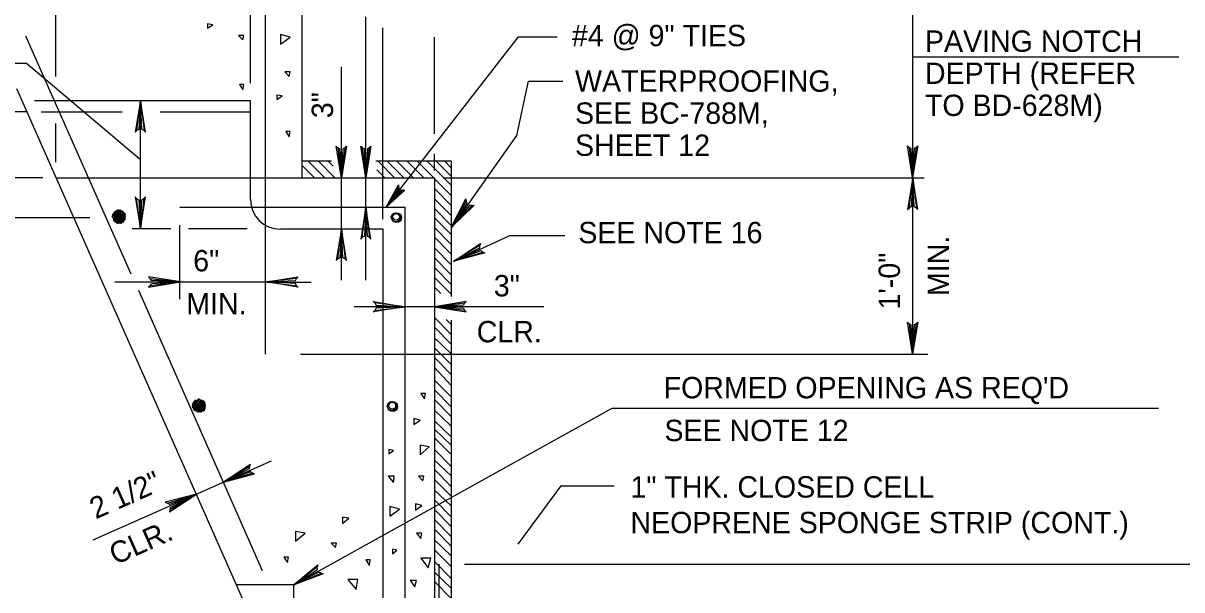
# Model space of a CAD drawing. Extents: x 640009 to 641706, y 298547 to 299735.
# Drawn here: x 640180 to 640342.7, y 299554.2 to 299633.8 of the extents above; entities that cross this region are included whole.
import ezdxf

# ---------------------------------------------------------------- set-up
doc = ezdxf.new("R2010")
doc.units = 0
doc.layers.add('1', color=7, linetype='Continuous')

msp = doc.modelspace()

# ---------------------------------------------------------------- linework, layer by layer
at = {"layer": '1'}
for p, q in [((640184.52, 299677.64), (640184.52, 299626.29)), ((640211.84, 299656.21), (640211.84, 299625.33)), ((640219.09, 299645.05), (640219.09, 299612.05)), ((640304.9, 299612.05), (640304.9, 299645.05)), ((640213.97, 299639.8), (640213.97, 299621.92)), ((640228.09, 299597.69), (640228.09, 299634.64)), ((640195.13, 299598.55), (640180.34, 299631.92)), ((640230.47, 299606.26), (640230.47, 299633.11)), ((640230.96, 299607.92), (640249.52, 299631.87)), ((640237.72, 299618.22), (640237.72, 299631.79)), ((640249.52, 299631.87), (640254.98, 299631.87)), ((640304.9, 299629.06), (640342.26, 299629.06)), ((640180.46, 299628.12), (640169.34, 299628.12)), ((640196.43, 299614.59), (640180.46, 299628.12)), ((640224.66, 299597.69), (640224.66, 299627.62)), ((640249.31, 299617.99), (640250.95, 299625.64)), ((640250.95, 299625.64), (640255.77, 299625.64)), ((640217.97, 299536.8), (640179.09, 299624.55)), ((640181.56, 299622.92), (640211.84, 299622.92)), ((640196.43, 299604.92), (640196.43, 299622.92)), ((640211.84, 299622.92), (640211.84, 299609.05)), ((640180.59, 299621.3), (640113.97, 299621.3)), ((640182.52, 299621.3), (640193.89, 299621.3)), ((640199.23, 299621.3), (640211.84, 299621.3)), ((640213.97, 299621.92), (640213.97, 299587.3)), ((640184.52, 299619.67), (640184.52, 299614.26)), ((640240.11, 299604.98), (640249.31, 299617.99)), ((640219.09, 299614.42), (640223.26, 299614.42)), ((640229.5, 299614.42), (640240.1, 299614.42)), ((640237.72, 299613.09), (640237.72, 299615.42)), ((640240.1, 299614.42), (640240.1, 299595.41)), ((640182.71, 299612.05), (640127.71, 299612.05)), ((640184.63, 299612.05), (640219.09, 299612.05)), ((640219.09, 299612.05), (640237.72, 299612.05)), ((640237.72, 299612.05), (640237.72, 299536.8)), ((640238.96, 299612.05), (640306.53, 299612.05)), ((640304.9, 299587.3), (640304.9, 299612.05)), ((640201.97, 299607.92), (640233.59, 299607.92)), ((640233.59, 299607.92), (640233.59, 299545.67)), ((640189.34, 299606.42), (640155.73, 299606.42)), ((640200.72, 299604.92), (640195.27, 299604.92)), ((640201.97, 299595.05), (640201.97, 299605.42)), ((640211.44, 299604.92), (640203.17, 299604.92)), ((640216.09, 299604.92), (640230.47, 299604.92)), ((640230.47, 299604.92), (640230.47, 299536.8)), ((640240.42, 299600.3), (640248.21, 299603.93)), ((640256.02, 299603.93), (640248.21, 299603.93)), ((640214.34, 299597.42), (640192.84, 299597.42)), ((640213.59, 299556.92), (640196.22, 299596.25)), ((640214.22, 299597.42), (640220.4, 299597.42)), ((640253.1, 299593.96), (640226.46, 299593.96)), ((640240.1, 299592.08), (640240.1, 299507.18)), ((640218.94, 299587.3), (640307.03, 299587.3)), ((640217.97, 299554.92), (640262.67, 299579.74)), ((640262.67, 299579.74), (640339.42, 299579.74)), ((640214.8, 299572.3), (640189.77, 299561.21)), ((640249.51, 299560.65), (640255.54, 299568.83)), ((640255.54, 299568.83), (640262.98, 299568.83)), ((640238.34, 299557.82), (640238.34, 299538.55)), ((640241.97, 299557.82), (640366.22, 299557.82)), ((640217.97, 299554.92), (640209.97, 299554.92)), ((640217.97, 299536.8), (640217.97, 299554.92))]:
    msp.add_line(p, q, dxfattribs=at)
for points in [[(640205.84, 299633.05), (640206.59, 299633.55), (640205.84, 299633.67)], [(640210.22, 299632.05), (640210.84, 299631.42), (640210.97, 299632.05)], [(640216.09, 299630.8), (640217.47, 299631.8), (640216.09, 299632.17)], [(640216.72, 299626.92), (640217.34, 299626.3), (640217.47, 299626.92)], [(640210.34, 299625.17), (640210.84, 299624.42), (640210.97, 299625.17)], [(640215.59, 299623.05), (640216.34, 299623.55), (640215.59, 299623.67)], [(640216.84, 299618.55), (640217.34, 299617.8), (640217.47, 299618.55)], [(640235.84, 299581.8), (640236.34, 299581.05), (640236.47, 299581.8)], [(640234.84, 299577.42), (640235.72, 299578.05), (640234.84, 299578.3)], [(640231.34, 299573.3), (640231.97, 299573.8), (640231.34, 299573.92)], [(640235.72, 299573.17), (640236.97, 299574.3), (640235.72, 299574.55)], [(640231.22, 299570.17), (640231.97, 299569.3), (640232.09, 299570.17)], [(640235.47, 299570.17), (640236.09, 299569.55), (640236.22, 299570.17)], [(640231.47, 299564.55), (640232.84, 299565.55), (640231.47, 299565.92)], [(640235.09, 299565.42), (640235.97, 299566.05), (640235.09, 299566.3)], [(640224.84, 299563.55), (640225.72, 299564.3), (640224.84, 299564.42)], [(640218.22, 299561.05), (640219.59, 299562.17), (640218.22, 299562.42)], [(640235.22, 299562.17), (640235.84, 299561.42), (640235.97, 299562.17)], [(640223.22, 299560.8), (640223.84, 299560.17), (640223.97, 299560.8)], [(640216.59, 299558.8), (640217.09, 299558.05), (640217.22, 299558.8)], [(640231.84, 299559.3), (640232.47, 299559.8), (640231.84, 299559.92)], [(640235.84, 299558.67), (640236.84, 299557.3), (640237.22, 299558.67)], [(640228.09, 299558.42), (640228.59, 299557.67), (640228.72, 299558.42)], [(640225.59, 299555.67), (640226.72, 299554.3), (640226.97, 299555.67)], [(640234.34, 299555.55), (640234.97, 299554.67), (640235.22, 299555.55)]]:
    msp.add_lwpolyline(points, close=True, dxfattribs=at)
for points in [[(640196.97, 299618.68), (640196.65, 299618.85), (640196.43, 299622.92), (640196.97, 299618.68), (640197.16, 299618.47), (640196.43, 299622.92), (640196.23, 299618.85), (640195.93, 299618.7), (640196.43, 299622.92), (640195.71, 299618.47), (640195.93, 299618.7)], [(640225.19, 299616.29), (640224.88, 299616.12), (640224.66, 299612.05), (640225.19, 299616.29), (640225.38, 299616.5), (640224.66, 299612.05), (640224.46, 299616.12), (640224.15, 299616.28), (640224.66, 299612.05), (640223.93, 299616.5), (640224.15, 299616.28)], [(640228.63, 299616.29), (640228.31, 299616.12), (640228.09, 299612.05), (640228.63, 299616.29), (640228.81, 299616.5), (640228.09, 299612.05), (640227.89, 299616.12), (640227.59, 299616.28), (640228.09, 299612.05), (640227.37, 299616.5), (640227.59, 299616.28)], [(640305.42, 299616.34), (640305.11, 299616.16), (640304.89, 299612.09), (640305.42, 299616.34), (640305.61, 299616.55), (640304.89, 299612.09), (640304.69, 299616.16), (640304.38, 299616.32), (640304.89, 299612.09), (640304.16, 299616.55), (640304.38, 299616.32)], [(640220.88, 299612.05), (640219.09, 299613.84)], [(640222.35, 299612.05), (640219.94, 299614.45)], [(640223.76, 299612.05), (640221.38, 299614.42)], [(640223.49, 299613.69), (640222.76, 299614.42)], [(640232.13, 299612.05), (640229.76, 299614.42)], [(640233.42, 299612.05), (640231.04, 299614.42)], [(640234.8, 299612.05), (640232.42, 299614.42)], [(640236.24, 299612.05), (640233.86, 299614.42)], [(640240.1, 299609.57), (640235.24, 299614.42)], [(640240.1, 299611.01), (640236.68, 299614.42)], [(640240.1, 299612.27), (640237.94, 299614.42)], [(640240.1, 299613.46), (640239.13, 299614.42)], [(640230.76, 299612.05), (640229.63, 299613.18)], [(640233.31, 299610.33), (640233.06, 299610.32), (640230.96, 299607.92), (640233.31, 299610.33), (640233.56, 299610.33), (640230.96, 299607.92), (640232.81, 299610.57), (640232.68, 299610.82), (640230.96, 299607.92), (640232.67, 299611.07), (640232.68, 299610.82)], [(640305.44, 299607.8), (640305.12, 299607.98), (640304.9, 299612.05), (640305.44, 299607.8), (640305.63, 299607.59), (640304.9, 299612.05), (640304.7, 299607.98), (640304.4, 299607.82), (640304.9, 299612.05), (640304.18, 299607.59), (640304.4, 299607.82)], [(640195.89, 299609.17), (640196.21, 299608.99), (640196.43, 299604.92), (640195.89, 299609.17), (640195.71, 299609.38), (640196.43, 299604.92), (640196.63, 299608.99), (640196.93, 299609.15), (640196.43, 299604.92), (640197.16, 299609.38), (640196.93, 299609.15)], [(640240.1, 299608.19), (640237.72, 299610.57)], [(640240.1, 299606.75), (640237.72, 299609.13)], [(640243.04, 299608.17), (640242.68, 299608.22), (640240.1, 299605.07), (640243.04, 299608.17), (640243.32, 299608.23), (640240.1, 299605.07), (640242.34, 299608.46), (640242.19, 299608.77), (640240.1, 299605.07), (640242.15, 299609.09), (640242.19, 299608.77)], [(640192.47, 299606.55), (640193.34, 299607.55)], [(640192.47, 299606.42), (640193.59, 299607.55)], [(640192.47, 299606.55), (640193.47, 299607.55)], [(640192.47, 299606.67), (640193.34, 299607.55)], [(640192.47, 299606.8), (640193.22, 299607.55)], [(640192.59, 299606.3), (640193.72, 299607.55)], [(640192.59, 299606.05), (640193.97, 299607.42)], [(640192.59, 299606.17), (640193.84, 299607.42)], [(640192.59, 299606.3), (640193.72, 299607.42)], [(640192.59, 299606.92), (640192.97, 299607.42)], [(640192.72, 299606.05), (640193.97, 299607.42)], [(640228.63, 299603.68), (640228.31, 299603.85), (640228.09, 299607.92), (640228.63, 299603.68), (640228.81, 299603.47), (640228.09, 299607.92), (640227.89, 299603.85), (640227.59, 299603.7), (640228.09, 299607.92), (640227.37, 299603.47), (640227.59, 299603.7)], [(640240.1, 299605.37), (640237.72, 299607.75)], [(640192.72, 299605.92), (640194.09, 299607.3)], [(640192.84, 299605.92), (640194.09, 299607.3)], [(640192.84, 299605.8), (640194.22, 299607.17)], [(640192.97, 299605.8), (640194.22, 299607.17)], [(640192.97, 299605.8), (640194.22, 299607.05)], [(640193.09, 299605.67), (640194.34, 299607.05)], [(640193.09, 299605.67), (640194.34, 299606.92)], [(640193.22, 299605.67), (640194.34, 299606.92)], [(640193.22, 299605.67), (640194.34, 299606.8)], [(640193.34, 299605.67), (640194.34, 299606.67)], [(640193.47, 299605.67), (640194.34, 299606.55)], [(640193.59, 299605.67), (640194.34, 299606.42)], [(640193.72, 299605.67), (640194.34, 299606.3)], [(640193.97, 299605.8), (640194.22, 299606.05)], [(640240.1, 299604.09), (640237.72, 299606.46)], [(640225.19, 299600.68), (640224.88, 299600.85), (640224.66, 299604.92), (640225.19, 299600.68), (640225.38, 299600.47), (640224.66, 299604.92), (640224.46, 299600.85), (640224.15, 299600.7), (640224.66, 299604.92), (640223.93, 299600.47), (640224.15, 299600.7)], [(640240.1, 299602.71), (640237.72, 299605.09)], [(640240.1, 299601.36), (640237.72, 299603.75)], [(640244.55, 299601.61), (640244.26, 299601.83), (640240.45, 299600.38), (640244.55, 299601.61), (640244.81, 299601.53), (640240.45, 299600.38), (640244.09, 299602.22), (640244.11, 299602.56), (640240.45, 299600.38), (640244.22, 299602.85), (640244.11, 299602.56)], [(640240.1, 299599.84), (640237.72, 299602.21)], [(640240.1, 299598.46), (640237.72, 299600.84)], [(640240.1, 299597.09), (640237.72, 299599.46)], [(640197.81, 299596.9), (640197.98, 299597.22), (640202.05, 299597.44), (640197.81, 299596.9), (640197.59, 299596.72), (640202.05, 299597.44), (640197.98, 299597.64), (640197.82, 299597.94), (640202.05, 299597.44), (640197.59, 299598.16), (640197.82, 299597.94)], [(640218.38, 299596.9), (640218.21, 299597.22), (640214.14, 299597.44), (640218.38, 299596.9), (640218.59, 299596.72), (640214.14, 299597.44), (640218.21, 299597.64), (640218.37, 299597.94), (640214.14, 299597.44), (640218.59, 299598.16), (640218.37, 299597.94)], [(640240.1, 299595.71), (640237.72, 299598.09)], [(640238.61, 299595.84), (640237.72, 299596.73)], [(640229.35, 299594.5), (640229.53, 299594.18), (640233.59, 299593.96), (640229.35, 299594.5), (640229.14, 299594.68), (640233.59, 299593.96), (640229.53, 299593.76), (640229.37, 299593.46), (640233.59, 299593.96), (640229.14, 299593.24), (640229.37, 299593.46)], [(640241.96, 299594.5), (640241.79, 299594.18), (640237.72, 299593.96), (640241.96, 299594.5), (640242.17, 299594.68), (640237.72, 299593.96), (640241.79, 299593.76), (640241.95, 299593.46), (640237.72, 299593.96), (640242.17, 299593.24), (640241.95, 299593.46)], [(640240.1, 299590.09), (640237.72, 299592.46)], [(640240.1, 299588.71), (640237.72, 299591.09)], [(640240.1, 299591.46), (640239.4, 299592.16)], [(640305.42, 299591.59), (640305.11, 299591.41), (640304.89, 299587.34), (640305.42, 299591.59), (640305.61, 299591.8), (640304.89, 299587.34), (640304.69, 299591.41), (640304.38, 299591.57), (640304.89, 299587.34), (640304.16, 299591.8), (640304.38, 299591.57)], [(640240.1, 299587.36), (640237.72, 299589.59)], [(640240.1, 299585.84), (640237.72, 299588.21)], [(640240.1, 299584.46), (640237.72, 299586.84)], [(640240.1, 299582.89), (640237.72, 299585.46)], [(640240.1, 299581.31), (640237.72, 299583.68)], [(640240.1, 299579.93), (640237.72, 299582.31)], [(640203.72, 299580.05), (640204.59, 299581.05)], [(640203.72, 299579.8), (640204.84, 299581.05)], [(640203.72, 299579.92), (640204.72, 299581.05)], [(640203.72, 299580.05), (640204.72, 299581.05)], [(640203.72, 299580.17), (640204.59, 299581.05)], [(640203.72, 299580.3), (640204.47, 299580.92)], [(640203.84, 299579.55), (640205.09, 299580.92)], [(640203.84, 299579.67), (640205.09, 299580.92)], [(640203.84, 299579.67), (640204.97, 299580.92)], [(640203.84, 299580.42), (640204.22, 299580.92)], [(640203.97, 299579.42), (640205.34, 299580.8)], [(640203.97, 299579.42), (640205.22, 299580.8)], [(640203.97, 299579.55), (640205.22, 299580.8)], [(640204.09, 299579.3), (640205.34, 299580.67)], [(640204.22, 299579.3), (640205.47, 299580.67)], [(640204.22, 299579.3), (640205.47, 299580.55)], [(640204.34, 299579.17), (640205.47, 299580.42)], [(640204.34, 299579.17), (640205.59, 299580.42)], [(640204.34, 299579.17), (640205.47, 299580.42)], [(640204.47, 299579.17), (640205.59, 299580.3)], [(640204.59, 299579.17), (640205.59, 299580.17)], [(640204.72, 299579.17), (640205.59, 299580.05)], [(640204.84, 299579.17), (640205.59, 299579.92)], [(640204.97, 299579.17), (640205.59, 299579.8)], [(640240.1, 299578.56), (640237.72, 299580.93)], [(640205.22, 299579.3), (640205.47, 299579.55)], [(640240.1, 299577.21), (640237.72, 299579.43)], [(640240.1, 299575.72), (640237.72, 299577.95)], [(640240.1, 299574.54), (640237.72, 299576.76)], [(640239.97, 299573.31), (640237.72, 299575.55)], [(640240.1, 299571.56), (640237.72, 299573.93)], [(640211.76, 299571.57), (640211.73, 299571.21), (640208.11, 299569.34), (640211.76, 299571.57), (640211.88, 299571.82), (640208.11, 299569.34), (640211.9, 299570.82), (640212.17, 299570.61), (640208.11, 299569.34), (640212.47, 299570.5), (640212.17, 299570.61)], [(640240.1, 299570.21), (640237.72, 299572.43)], [(640240.1, 299568.74), (640237.72, 299571.11)], [(640240.1, 299567.36), (640237.72, 299569.74)], [(640200.63, 299565.45), (640200.67, 299565.81), (640204.3, 299567.65), (640200.63, 299565.45), (640200.52, 299565.19), (640204.3, 299567.65), (640200.5, 299566.19), (640200.23, 299566.41), (640204.3, 299567.65), (640199.93, 299566.52), (640200.23, 299566.41)], [(640240.1, 299566.01), (640237.72, 299568.24)], [(640240.1, 299564.49), (640237.72, 299566.86)], [(640240.1, 299563.11), (640237.72, 299565.49)], [(640240.1, 299561.74), (640237.72, 299564.11)], [(640240.1, 299560.36), (640237.72, 299562.74)], [(640240.1, 299559.01), (640237.72, 299561.24)], [(640240.1, 299557.49), (640237.72, 299559.86)], [(640221.82, 299556.55), (640221.51, 299556.73), (640217.88, 299554.87), (640221.82, 299556.55), (640222.1, 299556.49), (640217.88, 299554.87), (640221.3, 299557.09), (640221.28, 299557.43), (640217.88, 299554.87), (640221.37, 299557.74), (640221.28, 299557.43)], [(640240.1, 299555.83), (640237.72, 299558.21)], [(640240.1, 299554.48), (640237.72, 299556.71)], [(640240.1, 299553.01), (640237.72, 299555.38)]]:
    msp.add_lwpolyline(points, dxfattribs=at)
for centre, radius in [((640232.31, 299606.53), 0.636), ((640232.42, 299606.47), 0.693), ((640232.36, 299606.58), 0.474), ((640231.75, 299580.02), 0.636), ((640231.87, 299579.96), 0.693), ((640231.81, 299580.08), 0.474)]:
    msp.add_circle(centre, radius, dxfattribs=at)
msp.add_arc((640216.04, 299609), 4.13, 180, 270, dxfattribs=at)

# ---------------------------------------------------------------- texts
for s, p in [('#4 @ 9" TIES', (640257.04, 299630.53)), ('PAVING NOTCH', (640306.62, 299629.74)), ('WATERPROOFING,', (640257.48, 299624.14)), ('DEPTH (REFER', (640306.62, 299625.24)), ('TO BD-628M)', (640306.62, 299620.74)), ('SEE BC-788M,', (640257.48, 299619.64)), ('SHEET 12', (640257.48, 299615.14)), ('SEE NOTE 16', (640257.94, 299602.88)), (' 6"', (640202.74, 299598.93)), ('3"', (640246.07, 299595.42)), ('MIN.', (640202.88, 299592.89)), ('CLR.', (640243.67, 299588.97)), ("FORMED OPENING AS REQ'D", (640269.92, 299581.11)), ('SEE NOTE 12', (640270.03, 299575.1)), ('1" THK. CLOSED CELL', (640265.26, 299567.18)), ('NEOPRENE SPONGE STRIP (CONT.)', (640265.26, 299562.18))]:
    msp.add_text(s, height=3, dxfattribs=at).set_placement(p)
for s, rotation, p in [('3"', 90, (640223.49, 299620.43)), ('MIN.', 90, (640310.01, 299595.45)), ('1\'-0"', 90, (640303.11, 299593.57)), ('2 1/2"', 23.8943, (640190.16, 299564.11)), ('CLR.', 23.8943, (640192.91, 299557.68))]:
    msp.add_text(s, height=3, rotation=rotation, dxfattribs=at).set_placement(p)

doc.saveas('drawing.dxf')
